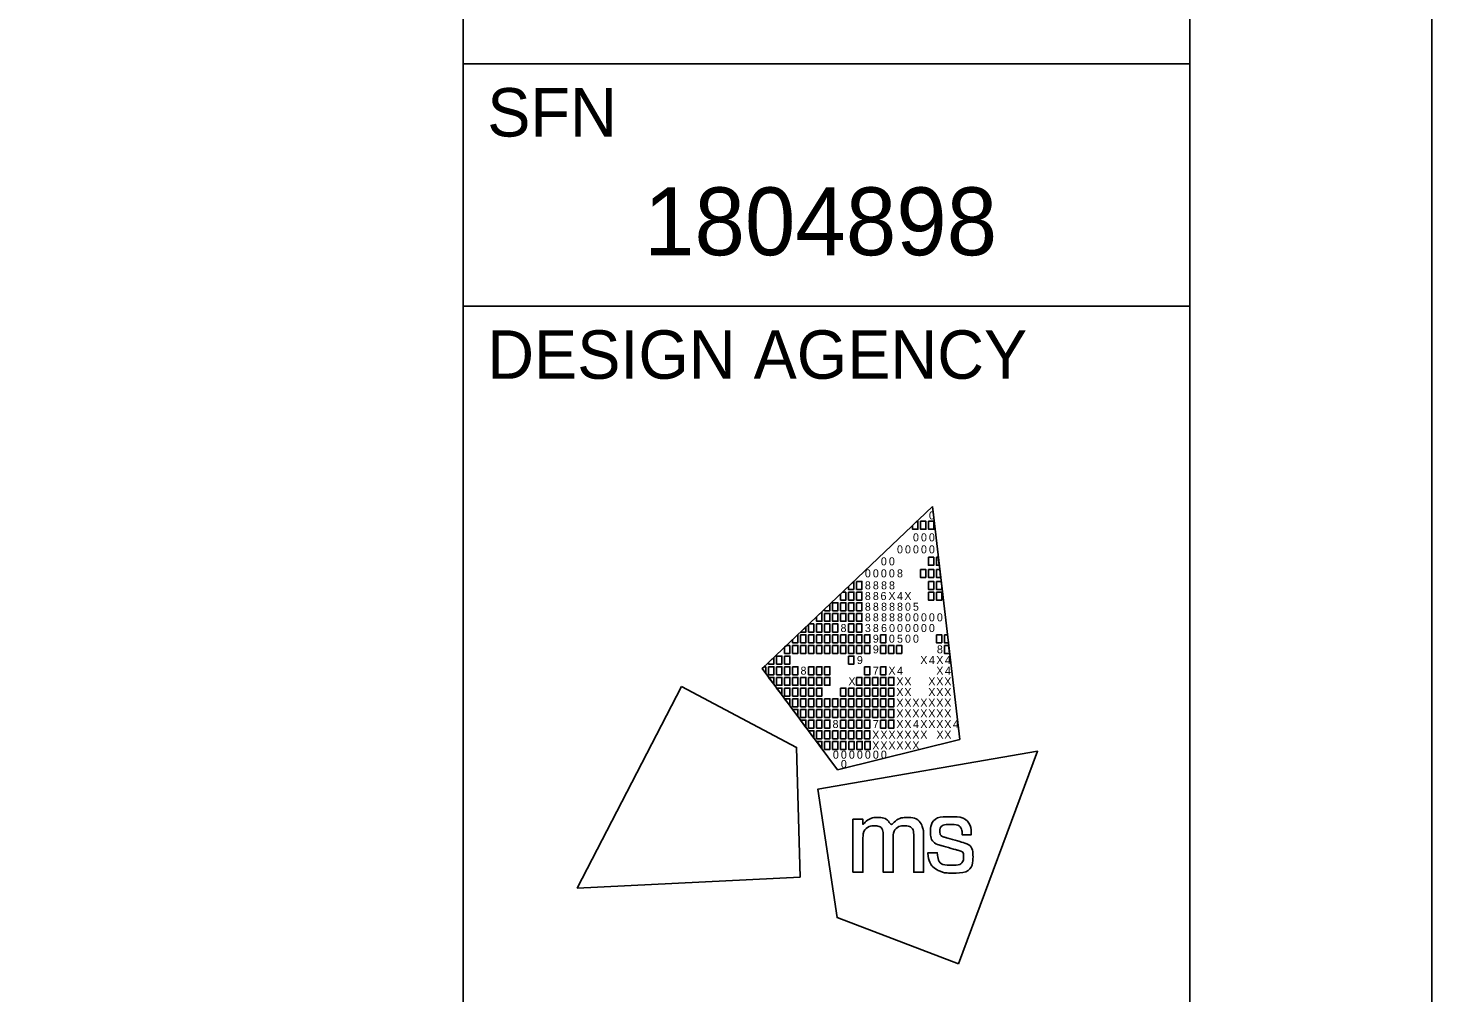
# Model space of a CAD drawing. Extents: x 0 to 34, y 0 to 22.
# Drawn here: x 31.102 to 34, y 3.582 to 5.574 of the extents above; entities that cross this region are included whole.
import ezdxf

# ---------------------------------------------------------------- set-up
doc = ezdxf.new("R2010")
doc.units = 0
for name, color, linetype in [('Default', 7, 'Continuous'), ('SH_Border', 7, 'Continuous'), ('SH_Cut_Line', 7, 'Continuous'), ('SH_Data', 7, 'Continuous')]:
    doc.layers.add(name, color=color, linetype=linetype)

msp = doc.modelspace()

# ---------------------------------------------------------------- linework, layer by layer
at = {"layer": 'Default'}
for p, q in [((32.6176, 4.2519), (32.9688, 4.5861)), ((32.9688, 4.5861), (32.9688, 4.5861)), ((32.9688, 4.5861), (33.0253, 4.1052)), ((32.773, 4.043), (32.6176, 4.2519)), ((33.0253, 4.1052), (32.773, 4.043))]:
    msp.add_line(p, q, dxfattribs=at)
for points in [[(32.9279, 4.5472), (32.9369, 4.5558), (32.939, 4.5558), (32.939, 4.5393), (32.9279, 4.5393)], [(32.9444, 4.5558), (32.9554, 4.5558), (32.9554, 4.5393), (32.9444, 4.5393)], [(32.9609, 4.5558), (32.9719, 4.5558), (32.9719, 4.5393), (32.9609, 4.5393)], [(32.9606, 4.4815), (32.9716, 4.4815), (32.9716, 4.465), (32.9606, 4.465)], [(32.9771, 4.4815), (32.9811, 4.4815), (32.983, 4.465), (32.9771, 4.465)], [(32.9442, 4.4567), (32.9552, 4.4567), (32.9552, 4.4402), (32.9442, 4.4402)], [(32.9606, 4.4567), (32.9716, 4.4567), (32.9716, 4.4402), (32.9606, 4.4402)], [(32.9771, 4.4567), (32.984, 4.4567), (32.9859, 4.4402), (32.9771, 4.4402)], [(32.7954, 4.4211), (32.8064, 4.4316), (32.8064, 4.4154), (32.7954, 4.4154)], [(32.7958, 4.4099), (32.8068, 4.4099), (32.8068, 4.3934), (32.7958, 4.3934)], [(32.8123, 4.4319), (32.8233, 4.4319), (32.8233, 4.4154), (32.8123, 4.4154)], [(32.8123, 4.4099), (32.8233, 4.4099), (32.8233, 4.3934), (32.8123, 4.3934)], [(32.9606, 4.4319), (32.9716, 4.4319), (32.9716, 4.4154), (32.9606, 4.4154)], [(32.9606, 4.4099), (32.9716, 4.4099), (32.9716, 4.3934), (32.9606, 4.3934)], [(32.9771, 4.4319), (32.9869, 4.4319), (32.9881, 4.4218), (32.9881, 4.4154), (32.9771, 4.4154)], [(32.9771, 4.4099), (32.9881, 4.4099), (32.9881, 4.3934), (32.9771, 4.3934)], [(32.7628, 4.3879), (32.7738, 4.3879), (32.7738, 4.3714), (32.7628, 4.3714)], [(32.7793, 4.3879), (32.7903, 4.3879), (32.7903, 4.3714), (32.7793, 4.3714)], [(32.7958, 4.3879), (32.8068, 4.3879), (32.8068, 4.3714), (32.7958, 4.3714)], [(32.8123, 4.3879), (32.8233, 4.3879), (32.8233, 4.3714), (32.8123, 4.3714)], [(32.7463, 4.3659), (32.7573, 4.3659), (32.7573, 4.3494), (32.7463, 4.3494)], [(32.7628, 4.3659), (32.7738, 4.3659), (32.7738, 4.3494), (32.7628, 4.3494)], [(32.7793, 4.3659), (32.7903, 4.3659), (32.7903, 4.3494), (32.7793, 4.3494)], [(32.7958, 4.3659), (32.8068, 4.3659), (32.8068, 4.3494), (32.7958, 4.3494)], [(32.8123, 4.3659), (32.8233, 4.3659), (32.8233, 4.3494), (32.8123, 4.3494)], [(32.6967, 4.3218), (32.7077, 4.3218), (32.7077, 4.3053), (32.6967, 4.3053)], [(32.7132, 4.3218), (32.7242, 4.3218), (32.7242, 4.3053), (32.7132, 4.3053)], [(32.7297, 4.3439), (32.7407, 4.3439), (32.7407, 4.3273), (32.7297, 4.3273)], [(32.7297, 4.3218), (32.7407, 4.3218), (32.7407, 4.3053), (32.7297, 4.3053)], [(32.7463, 4.3439), (32.7573, 4.3439), (32.7573, 4.3273), (32.7463, 4.3273)], [(32.7463, 4.3218), (32.7573, 4.3218), (32.7573, 4.3053), (32.7463, 4.3053)], [(32.7628, 4.3439), (32.7738, 4.3439), (32.7738, 4.3273), (32.7628, 4.3273)], [(32.7628, 4.3218), (32.7738, 4.3218), (32.7738, 4.3053), (32.7628, 4.3053)], [(32.7793, 4.3218), (32.7903, 4.3218), (32.7903, 4.3053), (32.7793, 4.3053)], [(32.7958, 4.3439), (32.8068, 4.3439), (32.8068, 4.3273), (32.7958, 4.3273)], [(32.7958, 4.3218), (32.8068, 4.3218), (32.8068, 4.3053), (32.7958, 4.3053)], [(32.8123, 4.3439), (32.8233, 4.3439), (32.8233, 4.3273), (32.8123, 4.3273)], [(32.8123, 4.3218), (32.8233, 4.3218), (32.8233, 4.3053), (32.8123, 4.3053)], [(32.8288, 4.3218), (32.8398, 4.3218), (32.8398, 4.3053), (32.8288, 4.3053)], [(32.8618, 4.3218), (32.8729, 4.3218), (32.8729, 4.3053), (32.8618, 4.3053)], [(32.9771, 4.3218), (32.9881, 4.3218), (32.9881, 4.3053), (32.9771, 4.3053)], [(32.9936, 4.3218), (32.9999, 4.3218), (33.0018, 4.3053), (32.9936, 4.3053)], [(32.6802, 4.2998), (32.6912, 4.2998), (32.6912, 4.2833), (32.6802, 4.2833)], [(32.6967, 4.2998), (32.7077, 4.2998), (32.7077, 4.2833), (32.6967, 4.2833)], [(32.7132, 4.2998), (32.7242, 4.2998), (32.7242, 4.2833), (32.7132, 4.2833)], [(32.7297, 4.2998), (32.7407, 4.2998), (32.7407, 4.2833), (32.7297, 4.2833)], [(32.7463, 4.2998), (32.7573, 4.2998), (32.7573, 4.2833), (32.7463, 4.2833)], [(32.7628, 4.2998), (32.7738, 4.2998), (32.7738, 4.2833), (32.7628, 4.2833)], [(32.7793, 4.2998), (32.7903, 4.2998), (32.7903, 4.2833), (32.7793, 4.2833)], [(32.7958, 4.2998), (32.8068, 4.2998), (32.8068, 4.2833), (32.7958, 4.2833)], [(32.8123, 4.2998), (32.8233, 4.2998), (32.8233, 4.2833), (32.8123, 4.2833)], [(32.8288, 4.2998), (32.8398, 4.2998), (32.8398, 4.2833), (32.8288, 4.2833)], [(32.8618, 4.2998), (32.8729, 4.2998), (32.8729, 4.2833), (32.8618, 4.2833)], [(32.8784, 4.2998), (32.8894, 4.2998), (32.8894, 4.2833), (32.8784, 4.2833)], [(32.8947, 4.2998), (32.9057, 4.2998), (32.9057, 4.2833), (32.8947, 4.2833)], [(32.9936, 4.2998), (33.0024, 4.2998), (33.0044, 4.2833), (32.9936, 4.2833)], [(32.6472, 4.2778), (32.6582, 4.2778), (32.6582, 4.2613), (32.6472, 4.2613)], [(32.6637, 4.2778), (32.6747, 4.2778), (32.6747, 4.2613), (32.6637, 4.2613)], [(32.7958, 4.2778), (32.8068, 4.2778), (32.8068, 4.2613), (32.7958, 4.2613)], [(32.6307, 4.2558), (32.6417, 4.2558), (32.6417, 4.2393), (32.6307, 4.2393)], [(32.6307, 4.2338), (32.6417, 4.2338), (32.6417, 4.22)], [(32.6472, 4.2558), (32.6582, 4.2558), (32.6582, 4.2393), (32.6472, 4.2393)], [(32.6472, 4.2338), (32.6582, 4.2338), (32.6582, 4.2173), (32.6472, 4.2173)], [(32.6637, 4.2558), (32.6747, 4.2558), (32.6747, 4.2393), (32.6637, 4.2393)], [(32.6637, 4.2338), (32.6747, 4.2338), (32.6747, 4.2173), (32.6637, 4.2173)], [(32.6802, 4.2558), (32.6912, 4.2558), (32.6912, 4.2393), (32.6802, 4.2393)], [(32.6802, 4.2338), (32.6912, 4.2338), (32.6912, 4.2173), (32.6802, 4.2173)], [(32.6967, 4.2338), (32.7077, 4.2338), (32.7077, 4.2173), (32.6967, 4.2173)], [(32.7132, 4.2558), (32.7242, 4.2558), (32.7242, 4.2393), (32.7132, 4.2393)], [(32.7132, 4.2338), (32.7242, 4.2338), (32.7242, 4.2173), (32.7132, 4.2173)], [(32.7297, 4.2558), (32.7407, 4.2558), (32.7407, 4.2393), (32.7297, 4.2393)], [(32.7297, 4.2338), (32.7407, 4.2338), (32.7407, 4.2173), (32.7297, 4.2173)], [(32.7463, 4.2558), (32.7573, 4.2558), (32.7573, 4.2393), (32.7463, 4.2393)], [(32.7463, 4.2338), (32.7573, 4.2338), (32.7573, 4.2173), (32.7463, 4.2173)], [(32.8123, 4.2338), (32.8233, 4.2338), (32.8233, 4.2173), (32.8123, 4.2173)], [(32.8288, 4.2558), (32.8398, 4.2558), (32.8398, 4.2393), (32.8288, 4.2393)], [(32.8288, 4.2338), (32.8398, 4.2338), (32.8398, 4.2173), (32.8288, 4.2173)], [(32.8453, 4.2338), (32.8563, 4.2338), (32.8563, 4.2173), (32.8453, 4.2173)], [(32.8618, 4.2558), (32.8729, 4.2558), (32.8729, 4.2393), (32.8618, 4.2393)], [(32.8618, 4.2338), (32.8729, 4.2338), (32.8729, 4.2173), (32.8618, 4.2173)], [(32.8784, 4.2338), (32.8894, 4.2338), (32.8894, 4.2173), (32.8784, 4.2173)], [(32.6472, 4.2117), (32.6582, 4.2117), (32.6582, 4.198)], [(32.6637, 4.2117), (32.6747, 4.2117), (32.6747, 4.1952), (32.6637, 4.1952)], [(32.6802, 4.2117), (32.6912, 4.2117), (32.6912, 4.1952), (32.6802, 4.1952)], [(32.6967, 4.2117), (32.7077, 4.2117), (32.7077, 4.1952), (32.6967, 4.1952)], [(32.7132, 4.2117), (32.7242, 4.2117), (32.7242, 4.1952), (32.7132, 4.1952)], [(32.7297, 4.2117), (32.7407, 4.2117), (32.7407, 4.1952), (32.7297, 4.1952)], [(32.7793, 4.2117), (32.7903, 4.2117), (32.7903, 4.1952), (32.7793, 4.1952)], [(32.7958, 4.2117), (32.8068, 4.2117), (32.8068, 4.1952), (32.7958, 4.1952)], [(32.8123, 4.2117), (32.8233, 4.2117), (32.8233, 4.1952), (32.8123, 4.1952)], [(32.8288, 4.2117), (32.8398, 4.2117), (32.8398, 4.1952), (32.8288, 4.1952)], [(32.8453, 4.2117), (32.8563, 4.2117), (32.8563, 4.1952), (32.8453, 4.1952)], [(32.8618, 4.2117), (32.8729, 4.2117), (32.8729, 4.1952), (32.8618, 4.1952)], [(32.8784, 4.2117), (32.8894, 4.2117), (32.8894, 4.1952), (32.8784, 4.1952)], [(32.6637, 4.1897), (32.6747, 4.1897), (32.6747, 4.176)], [(32.6747, 4.1897), (32.6747, 4.1897), (32.6747, 4.1897)], [(32.6802, 4.1897), (32.6912, 4.1897), (32.6912, 4.1732), (32.6802, 4.1732)], [(32.6967, 4.1897), (32.7077, 4.1897), (32.7077, 4.1732), (32.6967, 4.1732)], [(32.7132, 4.1897), (32.7242, 4.1897), (32.7242, 4.1732), (32.7132, 4.1732)], [(32.7297, 4.1897), (32.7407, 4.1897), (32.7407, 4.1732), (32.7297, 4.1732)], [(32.7463, 4.1897), (32.7573, 4.1897), (32.7573, 4.1732), (32.7463, 4.1732)], [(32.7628, 4.1897), (32.7738, 4.1897), (32.7738, 4.1732), (32.7628, 4.1732)], [(32.7793, 4.1897), (32.7903, 4.1897), (32.7903, 4.1732), (32.7793, 4.1732)], [(32.7958, 4.1897), (32.8068, 4.1897), (32.8068, 4.1732), (32.7958, 4.1732)], [(32.8123, 4.1897), (32.8233, 4.1897), (32.8233, 4.1732), (32.8123, 4.1732)], [(32.8288, 4.1897), (32.8398, 4.1897), (32.8398, 4.1732), (32.8288, 4.1732)], [(32.8453, 4.1897), (32.8563, 4.1897), (32.8563, 4.1732), (32.8453, 4.1732)], [(32.8618, 4.1897), (32.8729, 4.1897), (32.8729, 4.1732), (32.8618, 4.1732)], [(32.8784, 4.1897), (32.8894, 4.1897), (32.8894, 4.1732), (32.8784, 4.1732)], [(32.6802, 4.1677), (32.6912, 4.1677), (32.6912, 4.154)], [(32.7078, 4.1305), (32.6966, 4.1457), (32.7078, 4.1457)], [(32.6967, 4.1677), (32.7077, 4.1677), (32.7077, 4.1512), (32.6967, 4.1512)], [(32.7132, 4.1677), (32.7242, 4.1677), (32.7242, 4.1512), (32.7132, 4.1512)], [(32.7132, 4.1457), (32.7242, 4.1457), (32.7242, 4.1292), (32.7132, 4.1292)], [(32.7297, 4.1677), (32.7407, 4.1677), (32.7407, 4.1512), (32.7297, 4.1512)], [(32.7297, 4.1457), (32.7407, 4.1457), (32.7407, 4.1292), (32.7297, 4.1292)], [(32.7463, 4.1677), (32.7573, 4.1677), (32.7573, 4.1512), (32.7463, 4.1512)], [(32.7463, 4.1457), (32.7573, 4.1457), (32.7573, 4.1292), (32.7463, 4.1292)], [(32.7628, 4.1677), (32.7738, 4.1677), (32.7738, 4.1512), (32.7628, 4.1512)], [(32.7793, 4.1677), (32.7903, 4.1677), (32.7903, 4.1512), (32.7793, 4.1512)], [(32.7793, 4.1457), (32.7903, 4.1457), (32.7903, 4.1292), (32.7793, 4.1292)], [(32.7958, 4.1677), (32.8068, 4.1677), (32.8068, 4.1512), (32.7958, 4.1512)], [(32.7958, 4.1457), (32.8068, 4.1457), (32.8068, 4.1292), (32.7958, 4.1292)], [(32.8123, 4.1677), (32.8233, 4.1677), (32.8233, 4.1512), (32.8123, 4.1512)], [(32.8123, 4.1457), (32.8233, 4.1457), (32.8233, 4.1292), (32.8123, 4.1292)], [(32.8288, 4.1677), (32.8398, 4.1677), (32.8398, 4.1512), (32.8288, 4.1512)], [(32.8288, 4.1457), (32.8398, 4.1457), (32.8398, 4.1292), (32.8288, 4.1292)], [(32.8453, 4.1677), (32.8563, 4.1677), (32.8563, 4.1512), (32.8453, 4.1512)], [(32.8618, 4.1677), (32.8729, 4.1677), (32.8729, 4.1512), (32.8618, 4.1512)], [(32.8618, 4.1457), (32.8729, 4.1457), (32.8729, 4.1292), (32.8618, 4.1292)], [(32.8784, 4.1677), (32.8894, 4.1677), (32.8894, 4.1512), (32.8784, 4.1512)], [(32.8784, 4.1457), (32.8894, 4.1457), (32.8894, 4.1292), (32.8784, 4.1292)], [(32.724, 4.1082), (32.7132, 4.1237), (32.7242, 4.1237)], [(32.7297, 4.1237), (32.7407, 4.1237), (32.7407, 4.1072), (32.7297, 4.1072)], [(32.7463, 4.1237), (32.7573, 4.1237), (32.7573, 4.1072), (32.7463, 4.1072)], [(32.7628, 4.1237), (32.7738, 4.1237), (32.7738, 4.1072), (32.7628, 4.1072)], [(32.7793, 4.1237), (32.7903, 4.1237), (32.7903, 4.1072), (32.7793, 4.1072)], [(32.7958, 4.1237), (32.8068, 4.1237), (32.8068, 4.1072), (32.7958, 4.1072)], [(32.8123, 4.1237), (32.8233, 4.1237), (32.8233, 4.1072), (32.8123, 4.1072)], [(32.8288, 4.1237), (32.8398, 4.1237), (32.8398, 4.1072), (32.8288, 4.1072)], [(32.7302, 4.1017), (32.7407, 4.1017), (32.7408, 4.0875)], [(32.7463, 4.1017), (32.7573, 4.1017), (32.7573, 4.0852), (32.7463, 4.0852)], [(32.763, 4.1017), (32.774, 4.1017), (32.774, 4.0852), (32.763, 4.0852)], [(32.7794, 4.1017), (32.7904, 4.1017), (32.7904, 4.0852), (32.7794, 4.0852)], [(32.7961, 4.1017), (32.8071, 4.1017), (32.8071, 4.0852), (32.7961, 4.0852)], [(32.813, 4.1017), (32.824, 4.1017), (32.824, 4.0851), (32.813, 4.0851)], [(32.8296, 4.1017), (32.8407, 4.1017), (32.8407, 4.0851), (32.8296, 4.0851)]]:
    msp.add_lwpolyline(points, close=True, dxfattribs=at)
for points in [[(32.7903, 4.4099), (32.7836, 4.4099), (32.7793, 4.4058), (32.7793, 4.3934), (32.7903, 4.3934), (32.7903, 4.4099)], [(32.7573, 4.3849), (32.7463, 4.3744), (32.7463, 4.3714), (32.7573, 4.3714), (32.7573, 4.3849)], [(32.7407, 4.3691), (32.7297, 4.3587), (32.7297, 4.3494), (32.7407, 4.3494), (32.7407, 4.3691)], [(32.6912, 4.322), (32.6802, 4.3115), (32.6802, 4.3053), (32.6912, 4.3053), (32.6912, 4.322)], [(32.7077, 4.3377), (32.6968, 4.3273), (32.7077, 4.3273), (32.7077, 4.3377)], [(32.7242, 4.3439), (32.7142, 4.3439), (32.7132, 4.343), (32.7132, 4.3273), (32.7242, 4.3273), (32.7242, 4.3439)], [(32.6747, 4.2998), (32.6679, 4.2998), (32.6637, 4.2958), (32.6637, 4.2833), (32.6747, 4.2833), (32.6747, 4.2998)], [(32.6417, 4.2749), (32.6307, 4.2644), (32.6307, 4.2613), (32.6417, 4.2613), (32.6417, 4.2749)], [(32.6252, 4.2558), (32.6216, 4.2558), (32.6176, 4.2519), (32.6252, 4.2417), (32.6252, 4.2558)], [(32.4512, 4.2149), (32.2359, 3.7988), (32.6957, 3.8215), (32.6884, 4.0892), (32.4512, 4.2149)], [(33.0229, 3.6422), (33.1859, 4.0814), (32.7324, 4.0029), (32.7722, 3.7381), (33.0229, 3.6422)]]:
    msp.add_lwpolyline(points, dxfattribs=at)
for points in [[(32.8048, 3.8315), (32.8048, 3.8315), (32.8048, 3.9409), (32.8048, 3.9409), (32.8048, 3.9409), (32.8255, 3.9409), (32.8255, 3.9409), (32.8255, 3.9409), (32.8255, 3.9297), (32.8255, 3.9297), (32.8346, 3.9399), (32.8457, 3.9445), (32.8555, 3.9445), (32.8689, 3.9445), (32.8792, 3.9372), (32.8837, 3.9266), (32.8915, 3.9381), (32.905, 3.9446), (32.9166, 3.9446), (32.9325, 3.9446), (32.9451, 3.935), (32.9494, 3.9213), (32.9494, 3.9212), (32.9494, 3.9212), (32.9495, 3.9212), (32.9501, 3.919), (32.9507, 3.9172), (32.9507, 3.9071), (32.9507, 3.9071), (32.9507, 3.8314), (32.9507, 3.8314), (32.9507, 3.8314), (32.9303, 3.8314), (32.9303, 3.8314), (32.9303, 3.8314), (32.9303, 3.9048), (32.9303, 3.9048), (32.9303, 3.9201), (32.9219, 3.9274), (32.9111, 3.9274), (32.8995, 3.9274), (32.888, 3.9171), (32.888, 3.9001), (32.888, 3.9001), (32.888, 3.8315), (32.888, 3.8315), (32.888, 3.8315), (32.8674, 3.8315), (32.8674, 3.8315), (32.8674, 3.8315), (32.8674, 3.9059), (32.8674, 3.9059), (32.8674, 3.9203), (32.8588, 3.9274), (32.8497, 3.9274), (32.8384, 3.9274), (32.8254, 3.917), (32.8254, 3.8962), (32.8254, 3.8962), (32.8254, 3.8315), (32.8254, 3.8315), (32.8254, 3.8315), (32.8048, 3.8315), (32.8048, 3.8315)], [(32.9596, 3.8709), (32.9596, 3.8709), (32.9595, 3.8717), (32.9595, 3.8717), (32.9595, 3.8717), (32.9603, 3.8717), (32.9603, 3.8717), (32.9603, 3.8717), (32.9783, 3.8717), (32.9783, 3.8717), (32.9783, 3.8717), (32.9789, 3.8717), (32.9789, 3.8717), (32.9789, 3.8717), (32.979, 3.871), (32.979, 3.871), (32.9803, 3.8554), (32.9887, 3.846), (33.009, 3.846), (33.0273, 3.846), (33.0333, 3.8554), (33.0333, 3.8631), (33.0333, 3.8732), (33.0256, 3.8758), (33.0175, 3.878), (33.0175, 3.878), (32.987, 3.8867), (32.987, 3.8867), (32.9721, 3.8909), (32.9648, 3.9019), (32.9648, 3.9142), (32.9648, 3.9303), (32.9768, 3.9462), (33.0052, 3.9462), (33.0348, 3.9462), (33.0489, 3.9285), (33.0489, 3.9095), (33.0489, 3.9095), (33.0489, 3.9087), (33.0489, 3.9087), (33.0489, 3.9087), (33.0482, 3.9087), (33.0482, 3.9087), (33.0482, 3.9087), (33.0312, 3.9087), (33.0312, 3.9087), (33.0312, 3.9087), (33.0305, 3.9087), (33.0305, 3.9087), (33.0305, 3.9087), (33.0305, 3.9094), (33.0305, 3.9094), (33.0302, 3.9208), (33.0227, 3.93), (33.0056, 3.93), (32.9891, 3.93), (32.9843, 3.9218), (32.9843, 3.9157), (32.9843, 3.9108), (32.9869, 3.9059), (32.9959, 3.9033), (32.9959, 3.9033), (33.0255, 3.8948), (33.0255, 3.8948), (33.0462, 3.8889), (33.0527, 3.8777), (33.0527, 3.8639), (33.0527, 3.8462), (33.041, 3.8298), (33.0087, 3.8298), (32.9952, 3.8298), (32.9877, 3.8321), (32.9823, 3.8348), (32.9691, 3.8414), (32.961, 3.8536), (32.9596, 3.8709)]]:
    msp.add_open_spline(points, degree=3, dxfattribs=at)
at = {"layer": 'SH_Border'}
for p, q in [((32, 0.5), (32, 21.5)), ((32, 5.5), (33.5, 5.5)), ((32, 5), (33.5, 5))]:
    msp.add_line(p, q, dxfattribs=at)
msp.add_lwpolyline([(1.5, 21.5), (33.5, 21.5), (33.5, 0.5), (1.5, 0.5)], close=True, dxfattribs=at)
at = {"layer": 'SH_Cut_Line'}
msp.add_lwpolyline([(0, 0), (34, 0), (34, 22), (0, 22)], close=True, dxfattribs=at)
at = {"layer": 'SH_Data'}
msp.add_line((32.75, 4), (32.75, 4), dxfattribs=at)

# ---------------------------------------------------------------- texts
at = {"layer": 'Default'}
for s, p in [('0', (32.9617, 4.5597)), ('0', (32.9288, 4.5145)), ('0', (32.9453, 4.5145)), ('0', (32.9617, 4.5145)), ('0', (32.8958, 4.4897)), ('0', (32.9123, 4.4897)), ('0', (32.9288, 4.4897)), ('0', (32.9453, 4.4897)), ('0', (32.9617, 4.4897)), ('0', (32.8625, 4.465)), ('0', (32.8791, 4.465)), ('0', (32.8295, 4.4402)), ('0', (32.846, 4.4402)), ('0', (32.8625, 4.4402)), ('0', (32.8791, 4.4402)), ('8', (32.8958, 4.4402)), ('8', (32.8295, 4.4154)), ('8', (32.8295, 4.3934)), ('8', (32.846, 4.4154)), ('8', (32.846, 4.3934)), ('6', (32.8618, 4.3934)), ('8', (32.8629, 4.4154)), ('X', (32.8781, 4.3934)), ('8', (32.8793, 4.4154)), ('4', (32.8959, 4.3934)), ('X', (32.911, 4.3934)), ('8', (32.8295, 4.3713)), ('8', (32.846, 4.3713)), ('8', (32.8629, 4.3713)), ('8', (32.8794, 4.3713)), ('8', (32.8958, 4.3713)), ('0', (32.9123, 4.3713)), ('5', (32.9287, 4.3713)), ('8', (32.8295, 4.3494)), ('8', (32.846, 4.3494)), ('8', (32.8629, 4.3494)), ('8', (32.8794, 4.3494)), ('8', (32.8958, 4.3494)), ('0', (32.9123, 4.3494)), ('0', (32.9288, 4.3494)), ('0', (32.9453, 4.3494)), ('0', (32.9617, 4.3494)), ('0', (32.9782, 4.3494)), ('8', (32.7793, 4.3273)), ('3', (32.8295, 4.3273)), ('8', (32.846, 4.3273)), ('9', (32.846, 4.3053)), ('6', (32.8629, 4.3273)), ('0', (32.8791, 4.3053)), ('0', (32.8794, 4.3273)), ('0', (32.8958, 4.3273)), ('5', (32.8958, 4.3053)), ('0', (32.9123, 4.3273)), ('0', (32.9123, 4.3053)), ('0', (32.9288, 4.3273)), ('0', (32.9288, 4.3053)), ('0', (32.9453, 4.3273)), ('0', (32.9617, 4.3273)), ('9', (32.846, 4.2833)), ('8', (32.9782, 4.2833)), ('9', (32.813, 4.2613)), ('X', (32.9439, 4.2613)), ('4', (32.9617, 4.2613)), ('X', (32.9769, 4.2613)), ('4', (32.9947, 4.2613)), ('8', (32.6967, 4.2393)), ('X', (32.7955, 4.2173)), ('7', (32.846, 4.2393)), ('X', (32.8781, 4.2393)), ('X', (32.8945, 4.2173)), ('4', (32.8959, 4.2393)), ('X', (32.911, 4.2173)), ('X', (32.9604, 4.2173)), ('X', (32.9769, 4.2393)), ('X', (32.9769, 4.2173)), ('X', (32.9934, 4.2173)), ('4', (32.9947, 4.2393)), ('X', (32.8945, 4.1952)), ('X', (32.911, 4.1952)), ('X', (32.9604, 4.1952)), ('X', (32.9769, 4.1952)), ('X', (32.9934, 4.1952)), ('X', (32.8945, 4.1732)), ('X', (32.911, 4.1732)), ('X', (32.9275, 4.1732)), ('X', (32.9439, 4.1732)), ('X', (32.9604, 4.1732)), ('X', (32.9769, 4.1732)), ('X', (32.9934, 4.1732)), ('8', (32.7628, 4.1292)), ('7', (32.846, 4.1292)), ('X', (32.8945, 4.1512)), ('X', (32.8945, 4.1292)), ('X', (32.911, 4.1512)), ('X', (32.911, 4.1292)), ('X', (32.9275, 4.1512)), ('4', (32.9288, 4.1292)), ('X', (32.9439, 4.1512)), ('X', (32.9439, 4.1292)), ('X', (32.9604, 4.1512)), ('X', (32.9604, 4.1292)), ('X', (32.9769, 4.1512)), ('X', (32.9769, 4.1292)), ('X', (32.9934, 4.1512)), ('X', (32.9934, 4.1292)), ('4', (33.0112, 4.1292)), ('X', (32.8447, 4.1072)), ('X', (32.8616, 4.1072)), ('X', (32.8781, 4.1072)), ('X', (32.8945, 4.1072)), ('X', (32.911, 4.1072)), ('X', (32.9275, 4.1072)), ('X', (32.9439, 4.1072)), ('X', (32.9772, 4.1072)), ('X', (32.9934, 4.1072)), ('X', (32.8447, 4.0851)), ('X', (32.8616, 4.0851)), ('X', (32.8781, 4.0851)), ('X', (32.8945, 4.0851)), ('X', (32.911, 4.0851)), ('X', (32.9275, 4.0851)), ('0', (32.7635, 4.0659)), ('0', (32.78, 4.0659)), ('0', (32.78, 4.0467)), ('0', (32.7965, 4.0659)), ('0', (32.813, 4.0659)), ('0', (32.8295, 4.0659)), ('0', (32.846, 4.0659)), ('0', (32.8625, 4.0659))]:
    msp.add_text(s, height=0.0165, rotation=360, dxfattribs=at).set_placement(p)
at = {"layer": 'SH_Data'}
for s, height, p in [('SFN', 0.1, (32.05, 5.35)), ('1804898', 0.14, (32.3737, 5.105)), ('DESIGN AGENCY', 0.1, (32.05, 4.85))]:
    msp.add_text(s, height=height, dxfattribs=at).set_placement(p)

doc.saveas('drawing.dxf')
